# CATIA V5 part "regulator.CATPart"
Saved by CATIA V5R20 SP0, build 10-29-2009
Part number: r
Bounding box of the stored display mesh (mm): x -6 to 6, y -5.85 to 5.85, z 0 to 10
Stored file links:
  C:\Users\khanm\Downloads\Catia Project\Catia Project\regulator.CATPart
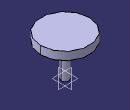
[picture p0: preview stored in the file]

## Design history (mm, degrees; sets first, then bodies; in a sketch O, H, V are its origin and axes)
Body1 (main body)
  Sketch1 on xy-plane, origin (0, 0, 0), H (1, 0, 0), V (0, 1, 0)
    circle A1 centre (0, 0) radius 1
    radius A1 = 1
  Pad1: profile Sketch1, direction (0, 0, 1), length 8
  Sketch2 on end face of Pad1, origin (0, 0, 8), H (1, 0, 0), V (0, 1, 0)
    circle A1 centre (0, 0) radius 6
    radius A1 = 6
  Pad2: profile Sketch2, direction (0, 0, 1), length 2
